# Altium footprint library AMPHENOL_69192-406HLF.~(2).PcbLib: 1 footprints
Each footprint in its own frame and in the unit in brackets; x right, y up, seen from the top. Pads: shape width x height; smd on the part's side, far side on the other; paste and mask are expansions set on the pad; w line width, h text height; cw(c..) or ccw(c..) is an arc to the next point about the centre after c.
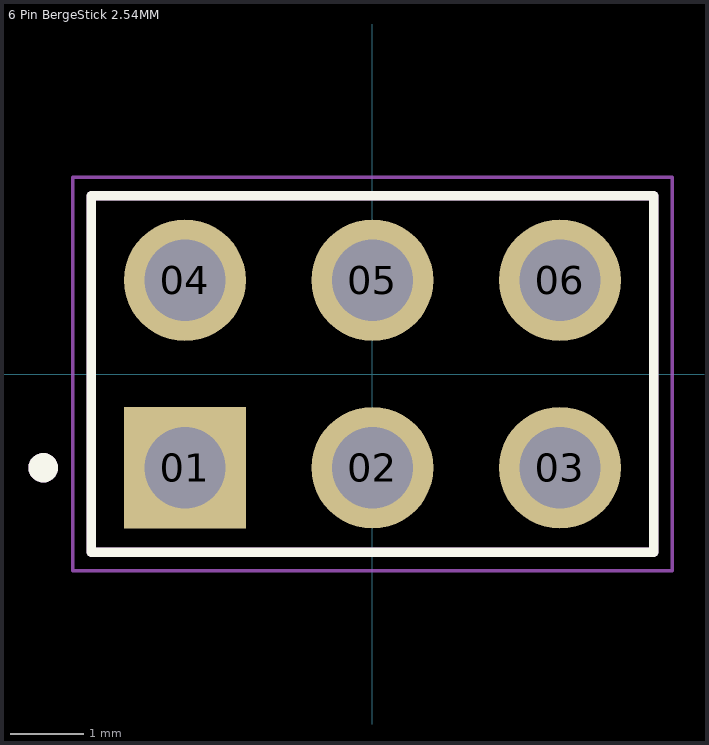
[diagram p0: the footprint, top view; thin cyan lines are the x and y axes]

## 6 Pin BergeStick 2.54MM [mm] "6 Pin 3X3Pos THT S/T BergeStick 2.54MM Amphenol 69192-406HLF AMPHENOL_69192-406HLF"
pads (6):
  rect 1.65x1.65 / inner round 1.65 / far side rect 1.65x1.65 hole 1.1: 01(-2.54,-1.27)
  round 1.65 hole 1.1: 02(0,-1.27) 03(2.54,-1.27) 04(-2.54,1.27) 05(0,1.27) 06(2.54,1.27)
Top Overlay:
  circle w0.2: c-4.46,-1.27 r0.1
  lines w0.127: -3.81,-2.415 3.81,-2.415 3.81,2.415 -3.81,2.415 -3.81,-2.415
Mechanical 13:
  circle w0.2: c-4.46,-1.27 r0.1
  lines w0.127: -3.81,-2.415 -3.81,2.415 ; -3.81,-2.415 3.81,-2.415 ; -3.81,-2.415 -3.81,2.415 ; -3.81,2.415 3.81,2.415 ; -3.81,2.415 3.81,2.415 ; 3.81,-2.415 3.81,2.415 ; 3.81,-2.415 3.81,2.415
Mechanical 15:
  lines w0.05: -4.06,-2.665 4.06,-2.665 4.06,2.665 -4.06,2.665 -4.06,-2.665
3D body "step_temp.STEP": height 8.38, standoff -3.05, extent -3.81,-2.415 3.81,2.415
